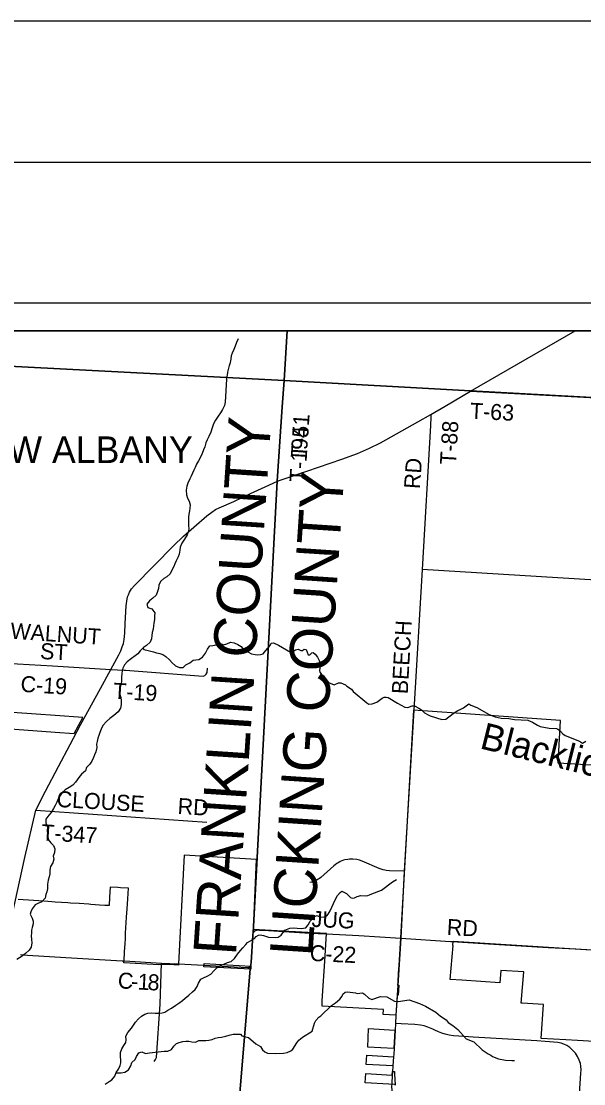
# Model space of a CAD drawing. Extents: x 0 to 91.3, y -0.7 to 22.
# Drawn here: x 4.012 to 6.008, y 18.226 to 22 of the extents above; entities that cross this region are included whole.
import ezdxf

# ---------------------------------------------------------------- set-up
doc = ezdxf.new("R2010")
doc.units = 0
for name, color, linetype in [('GM_X_City_Street', 7, 'Continuous'), ('GM_X_Corporation', 7, 'Continuous'), ('GM_X_Corporation_Text', 7, 'Continuous'), ('GM_X_County_Road', 7, 'Continuous'), ('GM_X_County_Road_Text', 7, 'Continuous'), ('GM_X_County_Text', 7, 'Continuous'), ('GM_X_Minor_River', 7, 'Continuous'), ('GM_X_Minor_River_Text', 7, 'Continuous'), ('GM_X_Township_Road', 7, 'Continuous'), ('GM_X_Township_Road_Text', 7, 'Continuous'), ('GM_X_US_Route', 7, 'Continuous'), ('SH_Border', 7, 'Continuous'), ('SH_Cut_Line', 7, 'Continuous'), ('SH_Data', 7, 'Continuous')]:
    doc.layers.add(name, color=color, linetype=linetype)

msp = doc.modelspace()

# ---------------------------------------------------------------- linework, layer by layer
at = {"layer": 'GM_X_City_Street'}
for points in [[(4.4838, 18.305), (4.4887, 18.3117), (4.492, 18.3195), (4.5045, 18.5078), (4.5099, 18.6546)], [(5.992, 18.1725), (5.9979, 18.2633), (5.9982, 18.2753), (5.9973, 18.2876), (5.9959, 18.2976), (5.992, 18.3093), (5.9862, 18.3221), (5.9787, 18.3341), (5.9686, 18.3455), (5.958, 18.3545), (5.9477, 18.3612), (5.9374, 18.3667), (5.9274, 18.3695), (5.9157, 18.372), (5.8708, 18.3756), (5.8418, 18.3776), (5.6158, 18.3912), (5.5645, 18.3943), (5.5453, 18.3957), (5.5303, 18.3985), (5.5161, 18.4021), (5.5038, 18.4052), (5.4921, 18.4102), (5.4798, 18.4163), (5.4723, 18.42), (5.4548, 18.4269), (5.4417, 18.4311), (5.4283, 18.4339), (5.4082, 18.4361), (5.3603, 18.4389), (5.3397, 18.44)]]:
    msp.add_lwpolyline(points, dxfattribs=at)
at = {"layer": 'GM_X_Corporation'}
for points in [[(4.9555, 20.9), (2.1, 20.9), (2.1, 20.8844), (2.3878, 20.8673), (3.0994, 20.8263), (3.2209, 20.8181), (3.3908, 20.8093), (3.4006, 20.8086), (3.9216, 20.777), (4.9448, 20.7239)], [(4.9555, 20.9), (2.1, 20.9), (2.1, 20.8844), (2.3878, 20.8673), (3.0994, 20.8263), (3.2209, 20.8181), (3.3908, 20.8093), (3.4006, 20.8086), (3.9216, 20.777), (4.9448, 20.7239)], [(8.9, 20.4953), (8.9, 20.9), (4.9555, 20.9), (4.9448, 20.7239), (5.6061, 20.6867), (6.253, 20.6521), (6.6637, 20.6293), (7.0477, 20.6033), (7.5521, 20.5793), (8.3956, 20.5276), (8.8785, 20.4965)], [(4.6607, 18.6526), (4.8269, 18.6431), (4.8262, 18.6322), (4.6603, 18.6415), (4.6603, 18.6415)], [(5.2447, 18.4218), (5.338, 18.4165), (5.334, 18.3504), (5.2412, 18.3558)], [(5.2384, 18.3274), (5.3323, 18.3216), (5.3303, 18.289), (5.2363, 18.2945)], [(5.3367, 18.261), (5.3388, 18.2209), (5.3387, 18.2227), (5.316, 18.2244), (5.2323, 18.2289), (5.2343, 18.2618), (5.3284, 18.2562), (5.3292, 18.2694), (5.3367, 18.2689)]]:
    msp.add_lwpolyline(points, close=True, dxfattribs=at)
for points in [[(4.7833, 18.1361), (4.8242, 18.6326), (4.8251, 18.6439), (4.8263, 18.646), (4.8271, 18.6491), (4.8277, 18.656), (4.8336, 18.7529), (4.834, 18.7568), (4.8352, 18.7619), (4.9205, 20.3667), (4.9376, 20.6305), (4.9448, 20.7239), (3.9216, 20.777), (3.4006, 20.8086), (3.3908, 20.8093), (3.2209, 20.8181), (3.0994, 20.8263), (2.3878, 20.8673), (2.1, 20.8844), (2.1, 14.1)], [(4.7833, 18.1361), (4.8242, 18.6326), (4.8251, 18.6439), (4.8263, 18.646), (4.8271, 18.6491), (4.8277, 18.656), (4.8336, 18.7529), (4.834, 18.7568), (4.8352, 18.7619), (4.9205, 20.3667), (4.9376, 20.6305), (4.9448, 20.7239), (3.9216, 20.777), (3.4006, 20.8086), (3.3908, 20.8093), (3.2209, 20.8181), (3.0994, 20.8263), (2.3878, 20.8673), (2.1, 20.8844), (2.1, 15.7138)], [(8.9, 14.1), (8.9, 20.9), (4.9555, 20.9), (4.9448, 20.7239), (4.9376, 20.6305), (4.9205, 20.3667), (4.8352, 18.7619), (4.834, 18.7568), (4.8336, 18.7529), (4.8277, 18.656), (4.8271, 18.6491), (4.8263, 18.646), (4.8251, 18.6439), (4.8242, 18.6326), (4.7833, 18.1361)], [(8.9, 15.2596), (8.9, 20.4953), (8.8785, 20.4965), (8.3956, 20.5276), (7.5521, 20.5793), (7.0477, 20.6033), (6.6637, 20.6293), (6.253, 20.6521), (5.6061, 20.6867), (4.9448, 20.7239), (4.9376, 20.6305), (4.9205, 20.3667), (4.8352, 18.7619), (4.834, 18.7568), (4.8336, 18.7529), (4.8277, 18.656), (4.8271, 18.6491), (4.8263, 18.646), (4.8251, 18.6439), (4.8242, 18.6326), (4.7833, 18.1361)], [(6.4311, 19.3332), (5.9167, 19.3643), (5.9255, 19.5165), (5.4044, 19.5531), (5.3577, 18.744), (5.353, 18.6658), (5.3518, 18.6467), (5.35, 18.6169), (5.3483, 18.5875), (5.3469, 18.5764), (5.352, 18.5761), (5.3498, 18.5405), (5.3457, 18.5407), (5.3444, 18.5224), (5.3433, 18.5047), (5.3422, 18.4869), (5.3412, 18.4694), (5.2963, 18.4714), (5.2971, 18.4894), (5.0792, 18.5014), (5.0803, 18.5206), (5.0814, 18.5382), (5.0893, 18.6616), (5.0956, 18.7589), (5.0723, 18.7602), (4.9856, 18.765), (4.9761, 18.7655), (4.9479, 18.7671), (4.9196, 18.7687), (4.8772, 18.7711), (4.8358, 18.7734), (4.8359, 18.7742), (4.8465, 19.0226), (4.5906, 19.0377), (4.5703, 18.6519), (4.5699, 18.6465), (4.5532, 18.6475), (4.5203, 18.6493), (4.5004, 18.6481), (4.376, 18.6553), (4.3768, 18.6665), (4.377, 18.6705), (4.3779, 18.6856), (4.3785, 18.695), (4.3802, 18.7228), (4.3813, 18.7417), (4.3824, 18.7606), (4.3836, 18.7795), (4.3847, 18.7984), (4.3858, 18.8174), (4.3876, 18.8465), (4.3897, 18.8824), (4.3908, 18.9013), (4.392, 18.9204), (4.3636, 18.9219), (4.3541, 18.9224), (4.3275, 18.9238), (4.3264, 18.906), (4.3253, 18.8881), (4.3236, 18.8584), (4.3086, 18.8593), (4.2897, 18.8606), (4.2589, 18.8627), (4.2519, 18.8631), (4.2174, 18.8654), (4.1862, 18.8675), (4.1767, 18.8681), (4.1325, 18.8711), (4.121, 18.8718), (4.0917, 18.8738), (4.0013, 18.8798)], [(3.8922, 19.4929), (4.1325, 19.475), (4.1996, 19.4699), (4.215, 19.4983), (4.2305, 19.5269), (4.1325, 19.5337), (4.0647, 19.5386), (3.9805, 19.5443)], [(6.045, 18.3762), (5.986, 18.3796), (5.9443, 18.382), (5.8573, 18.3869), (5.8648, 18.5077), (5.7899, 18.5122), (5.7859, 18.5125), (5.7955, 18.6235), (5.7138, 18.6282), (5.7104, 18.5841), (5.5748, 18.5934), (5.5342, 18.5965), (5.5448, 18.7169), (5.5439, 18.7169), (5.5451, 18.7322), (6.3918, 18.6787)]]:
    msp.add_lwpolyline(points, dxfattribs=at)
at = {"layer": 'GM_X_County_Road'}
for p, q in [((4.945, 20.7234), (4.9557, 20.9)), ((5.3586, 18.7432), (5.5353, 18.731)), ((4.5698, 18.6514), (4.6596, 18.6465))]:
    msp.add_line(p, q, dxfattribs=at)
for points in [[(3.8207, 19.7276), (3.8606, 19.7255), (3.9577, 19.7193), (4.1234, 19.7106), (4.3298, 19.697)], [(4.8253, 18.6433), (4.8265, 18.6455), (4.8273, 18.6485), (4.828, 18.6555), (4.8338, 18.7524), (4.8342, 18.7562), (4.8354, 18.7613)], [(4.8354, 18.7613), (4.8382, 18.7657), (4.8413, 18.7685), (4.8445, 18.7703), (4.8475, 18.7714), (4.851, 18.7719), (4.8569, 18.7718), (4.8896, 18.7699), (5.0362, 18.761), (5.0949, 18.758)], [(5.0949, 18.758), (5.2094, 18.7522), (5.3586, 18.7432)], [(5.5353, 18.731), (5.5363, 18.731), (5.5413, 18.7306), (5.6887, 18.7219), (5.882, 18.71), (5.98, 18.7044), (6.1355, 18.6949), (6.3006, 18.6844), (6.3651, 18.68), (6.3921, 18.6782)], [(4.0096, 18.6845), (4.0345, 18.6828), (4.1701, 18.6744), (4.3697, 18.6624)], [(4.3697, 18.6624), (4.3787, 18.6619), (4.5099, 18.6546), (4.5698, 18.6514)], [(4.6596, 18.6465), (4.7674, 18.6407), (4.8159, 18.6386), (4.8192, 18.6389), (4.8222, 18.6406), (4.8241, 18.6422), (4.8253, 18.6433)]]:
    msp.add_lwpolyline(points, dxfattribs=at)
at = {"layer": 'GM_X_Minor_River'}
for points in [[(4.7407, 20.7285), (4.744, 20.7428), (4.7455, 20.7535), (4.7488, 20.7675), (4.7514, 20.777), (4.754, 20.7873), (4.7566, 20.7998), (4.7585, 20.8124), (4.7611, 20.8223), (4.7678, 20.8356), (4.7727, 20.847), (4.7768, 20.8603), (4.7828, 20.8732)], [(4.7407, 20.7285), (4.736, 20.6464), (4.7336, 20.6351), (4.726, 20.6211), (4.7194, 20.6093), (4.7103, 20.5973), (4.7011, 20.5829), (4.6945, 20.5696), (4.6895, 20.5552), (4.6841, 20.5401), (4.6779, 20.5253), (4.6722, 20.5125), (4.6675, 20.5019), (4.6629, 20.4882), (4.6583, 20.4776), (4.654, 20.4648), (4.6471, 20.4496), (4.641, 20.439), (4.634, 20.4262), (4.629, 20.4152), (4.6248, 20.4054), (4.6198, 20.3948), (4.6148, 20.3845), (4.6098, 20.3747), (4.6036, 20.3596), (4.5998, 20.3486), (4.5974, 20.3338), (4.5981, 20.3182), (4.6018, 20.3061), (4.6074, 20.2954), (4.6108, 20.2817), (4.6107, 20.2707), (4.6091, 20.2609), (4.6068, 20.2495), (4.6059, 20.2381), (4.6051, 20.2226), (4.6054, 20.2074), (4.6061, 20.1979), (4.6052, 20.1884), (4.6006, 20.1755), (4.591, 20.16), (4.5814, 20.1464), (4.576, 20.1317), (4.5752, 20.121), (4.5728, 20.1074), (4.5686, 20.0972), (4.5621, 20.0832), (4.5571, 20.0726), (4.5532, 20.0627), (4.5467, 20.0506), (4.5398, 20.0374), (4.5283, 20.0261), (4.5184, 20.0208), (4.5062, 20.0103), (4.5004, 19.9966), (4.4988, 19.9845), (4.4957, 19.9746), (4.4907, 19.9614), (4.4789, 19.9501), (4.4671, 19.9407), (4.4575, 19.9297), (4.4608, 19.9179), (4.4749, 19.9133), (4.4854, 19.8988), (4.4849, 19.8882), (4.4845, 19.8753), (4.4829, 19.8616), (4.4817, 19.8518), (4.4797, 19.8408), (4.4766, 19.8283), (4.4758, 19.818), (4.4738, 19.8067), (4.4699, 19.7938), (4.4566, 19.7825), (4.4455, 19.7749), (4.4341, 19.7633), (4.426, 19.7534), (4.4161, 19.7455), (4.4035, 19.7357), (4.3879, 19.7244), (4.378, 19.7139), (4.3726, 19.7025), (4.3706, 19.6923), (4.3687, 19.6828), (4.3678, 19.6699), (4.3677, 19.6559), (4.3669, 19.6464), (4.3615, 19.6312), (4.3592, 19.6184), (4.3614, 19.6089), (4.3651, 19.5978), (4.3666, 19.5868), (4.3668, 19.5728), (4.3645, 19.5603), (4.3564, 19.547), (4.3404, 19.5335), (4.3263, 19.5233), (4.3145, 19.5127), (4.3019, 19.4988), (4.2953, 19.4852), (4.2903, 19.473)], [(4.4433, 19.7726), (4.4474, 19.7681), (4.4618, 19.765), (4.4716, 19.7619), (4.4815, 19.7599), (4.4917, 19.7565), (4.5035, 19.7541), (4.5148, 19.7503), (4.525, 19.7437), (4.5382, 19.7315), (4.5477, 19.7208), (4.5597, 19.7098), (4.573, 19.7044), (4.5859, 19.7039), (4.5962, 19.7133), (4.6099, 19.7209), (4.6225, 19.7303), (4.632, 19.7317), (4.6415, 19.7328), (4.6548, 19.7415), (4.6659, 19.7551), (4.6728, 19.7694), (4.6809, 19.7815), (4.6915, 19.7826), (4.7037, 19.7848), (4.7147, 19.7923), (4.7295, 19.7854), (4.7413, 19.788), (4.7542, 19.794), (4.7671, 19.792), (4.78, 19.7866), (4.7921, 19.7794), (4.8019, 19.7672), (4.8162, 19.7602), (4.8291, 19.7533), (4.8416, 19.7506), (4.8511, 19.7494), (4.861, 19.7505), (4.8705, 19.7531), (4.8793, 19.7648)], [(4.8793, 19.7648), (4.8953, 19.7821), (4.8983, 19.7904), (4.9067, 19.7919), (4.9245, 19.7838), (4.9676, 19.7593), (4.9741, 19.7597), (4.9794, 19.7631), (4.9847, 19.7668), (4.9942, 19.7694), (5.0041, 19.7645), (5.0098, 19.7644), (5.0155, 19.7693), (5.0231, 19.7682), (5.0298, 19.7488), (5.0359, 19.7491), (5.0427, 19.7559), (5.048, 19.7574), (5.0548, 19.7521), (5.0631, 19.741), (5.0691, 19.7288), (5.0729, 19.7167), (5.0732, 19.7095), (5.0697, 19.6931), (5.0716, 19.6874), (5.0757, 19.6817), (5.0848, 19.6752), (5.1025, 19.6512), (5.1226, 19.6428), (5.1382, 19.6495), (5.1465, 19.6495), (5.1624, 19.6433), (5.1677, 19.638), (5.1836, 19.6269), (5.1896, 19.6185), (5.2383, 19.5784), (5.2459, 19.5739), (5.2577, 19.5749), (5.2736, 19.5809), (5.2931, 19.5953), (5.2995, 19.5986), (5.3071, 19.5994), (5.3143, 19.5982), (5.3476, 19.5779), (5.3726, 19.5634), (5.3836, 19.5622), (5.3992, 19.5682), (5.4075, 19.5677), (5.4226, 19.5601), (5.4317, 19.5536), (5.4427, 19.5429), (5.4555, 19.536), (5.4631, 19.5322), (5.504, 19.5198), (5.5181, 19.5209), (5.5447, 19.5413), (5.5607, 19.5514), (5.5691, 19.5552)], [(5.5691, 19.5552), (5.5811, 19.5609), (5.5998, 19.5756), (5.6073, 19.5702), (5.6281, 19.5618), (5.6727, 19.5369), (5.6935, 19.5288), (5.7144, 19.5245), (5.7424, 19.5232), (5.7625, 19.5193), (5.8098, 19.5171), (5.8257, 19.5105), (5.8439, 19.4994), (5.8537, 19.4952), (5.8851, 19.4893), (5.9109, 19.4877), (5.9158, 19.4857), (5.9219, 19.4819), (5.9343, 19.4686), (5.9426, 19.4632), (5.9929, 19.4421), (6.0031, 19.4356), (6.0153, 19.4431)], [(4.2903, 19.473), (4.2868, 19.4628), (4.2841, 19.4533), (4.281, 19.4416), (4.2791, 19.4317), (4.2801, 19.42), (4.277, 19.4052), (4.272, 19.3942), (4.2681, 19.3844), (4.2624, 19.3715), (4.2555, 19.3605), (4.2436, 19.3492), (4.2394, 19.3371), (4.2253, 19.3258), (4.2161, 19.313), (4.205, 19.2975), (4.195, 19.2858), (4.1817, 19.2779), (4.1672, 19.2692), (4.1577, 19.2605), (4.1481, 19.2462), (4.1416, 19.2356), (4.1377, 19.2254), (4.1323, 19.214), (4.1258, 19.2038), (4.1181, 19.1898), (4.1101, 19.18), (4.099, 19.166), (4.0986, 19.1531), (4.1045, 19.1379), (4.1041, 19.1235), (4.1062, 19.1064), (4.1077, 19.0939), (4.1167, 19.0817), (4.1269, 19.0725), (4.1314, 19.0596), (4.1294, 19.0471), (4.1255, 19.0346), (4.1281, 19.0239), (4.1242, 19.0103), (4.1154, 18.9974), (4.1138, 18.9842), (4.1134, 18.9716), (4.1114, 18.9606), (4.1079, 18.9493), (4.1048, 18.9341), (4.1047, 18.9182), (4.1023, 18.908), (4.0989, 18.8981), (4.0973, 18.8852), (4.0847, 18.8716), (4.0713, 18.8664), (4.0614, 18.8608), (4.0507, 18.8475), (4.0457, 18.8369), (4.0434, 18.8275), (4.0505, 18.8134), (4.0539, 18.8027), (4.0542, 18.7933), (4.0507, 18.7808), (4.0487, 18.7709), (4.0479, 18.761), (4.0475, 18.7516), (4.0485, 18.7383), (4.05, 18.7257), (4.0468, 18.7113), (4.0399, 18.6996), (4.0273, 18.6879), (4.0148, 18.6793), (3.9968, 18.6668)], [(4.8148, 18.727), (4.84, 18.7416), (4.8461, 18.7484), (4.8541, 18.754), (4.8594, 18.7551), (4.8719, 18.7528), (4.8897, 18.7463), (4.9124, 18.7446), (4.9231, 18.7465), (4.9341, 18.754), (4.9471, 18.771), (4.965, 18.7778), (4.9764, 18.7796), (5.0052, 18.7776), (5.0212, 18.7794), (5.0299, 18.7907), (5.0372, 18.8028), (5.0525, 18.8195), (5.0616, 18.8228), (5.0752, 18.8178), (5.0874, 18.8185), (5.0961, 18.8227), (5.1007, 18.8276), (5.108, 18.8401), (5.126, 18.8791), (5.1345, 18.8938), (5.1436, 18.9052), (5.1497, 18.9097), (5.166, 18.902), (5.18, 18.8875), (5.1856, 18.8849), (5.1944, 18.8856), (5.2039, 18.8912), (5.2168, 18.8942), (5.2324, 18.8934), (5.2419, 18.8944), (5.2479, 18.8971), (5.2555, 18.9001), (5.2901, 18.9128), (5.3298, 18.9434), (5.3435, 18.9509)], [(4.3099, 18.2244), (4.3236, 18.2342), (4.3331, 18.2391), (4.3438, 18.2523), (4.3492, 18.2652), (4.3569, 18.2773), (4.3626, 18.2901), (4.3654, 18.3004), (4.365, 18.3106), (4.3647, 18.3212), (4.3641, 18.3368), (4.3687, 18.35), (4.3764, 18.3614), (4.3825, 18.372), (4.3845, 18.3818), (4.3827, 18.3951), (4.3896, 18.408), (4.4033, 18.4235), (4.4106, 18.434), (4.4179, 18.4443), (4.4278, 18.4567), (4.4381, 18.4654), (4.4507, 18.4729), (4.4606, 18.4763), (4.4727, 18.4773), (4.4872, 18.4765), (4.5001, 18.4764), (4.5122, 18.4775), (4.5217, 18.4805), (4.5324, 18.4868), (4.5453, 18.4947), (4.5602, 18.5049), (4.5712, 18.512), (4.5838, 18.5214), (4.5938, 18.5294), (4.6071, 18.5407), (4.6201, 18.5516), (4.6296, 18.5599), (4.6358, 18.5709), (4.6408, 18.583), (4.6496, 18.5966), (4.6591, 18.6022), (4.672, 18.6074), (4.6842, 18.6146), (4.6957, 18.6267), (4.7075, 18.6387), (4.7205, 18.6466), (4.7311, 18.6507), (4.7441, 18.6564), (4.7574, 18.6605), (4.7688, 18.6706), (4.7788, 18.6857), (4.7895, 18.699), (4.7987, 18.7088), (4.8094, 18.7209), (4.8148, 18.727)], [(4.7942, 18.3963), (4.8179, 18.3894), (4.844, 18.3673), (4.8607, 18.3585), (4.8682, 18.3467), (4.8761, 18.339), (4.8863, 18.3341), (4.9144, 18.3332), (4.9429, 18.3338), (4.9558, 18.3367), (4.9683, 18.342), (4.976, 18.3488), (4.9901, 18.3715), (4.9974, 18.3806), (5.0027, 18.3847), (5.0103, 18.3908), (5.0438, 18.4122), (5.0523, 18.4414), (5.0569, 18.4501), (5.068, 18.4626), (5.0753, 18.4664), (5.1123, 18.5041), (5.1271, 18.5135), (5.142, 18.5264), (5.1504, 18.5373), (5.1535, 18.5442), (5.1615, 18.5509), (5.1691, 18.5524), (5.1979, 18.5485), (5.2039, 18.5462), (5.2229, 18.5484), (5.2305, 18.5434), (5.2448, 18.53), (5.2562, 18.5247), (5.2866, 18.5355), (5.3097, 18.5339), (5.3362, 18.5193), (5.3495, 18.5178), (5.3886, 18.5236), (5.4254, 18.5113), (5.4465, 18.5017), (5.4836, 18.4795), (5.4995, 18.4658), (5.5199, 18.4524), (5.5274, 18.4432), (5.5437, 18.4329), (5.5611, 18.418)], [(4.3489, 18.2644), (4.3667, 18.2639), (4.38, 18.2673), (4.3929, 18.2751), (4.4013, 18.2888), (4.4048, 18.3013), (4.4163, 18.3122), (4.4213, 18.3224), (4.429, 18.3357), (4.4404, 18.339), (4.4532, 18.3329), (4.4665, 18.3351), (4.4772, 18.3365), (4.4874, 18.3376), (4.4981, 18.339), (4.5079, 18.3401), (4.5189, 18.3416), (4.5319, 18.3419), (4.5452, 18.3475), (4.5528, 18.3588), (4.5624, 18.369), (4.5723, 18.372), (4.5856, 18.3753), (4.5962, 18.3772), (4.6068, 18.3771), (4.6171, 18.3751), (4.63, 18.3736), (4.6425, 18.3788), (4.657, 18.3795), (4.6668, 18.3798), (4.6775, 18.3809), (4.6889, 18.3831), (4.6999, 18.3872), (4.7102, 18.3898), (4.7227, 18.3908), (4.7375, 18.3942), (4.7497, 18.3986), (4.7637, 18.4016), (4.7766, 18.4023), (4.7899, 18.4022), (4.7942, 18.3963)], [(5.5611, 18.418), (5.5904, 18.3856), (5.6177, 18.374), (5.6471, 18.3466), (5.669, 18.3324), (5.6788, 18.327), (5.6837, 18.3225), (5.7057, 18.3147), (5.7307, 18.3097), (5.753, 18.308), (5.7625, 18.3087)]]:
    msp.add_lwpolyline(points, dxfattribs=at)
at = {"layer": 'GM_X_Township_Road'}
for p, q in [((4.0635, 19.1971), (4.671, 19.1554)), ((5.3586, 18.7432), (5.3481, 18.5748)), ((5.3456, 18.5352), (5.3415, 18.4698)), ((5.3384, 18.4162), (5.3349, 18.3505)), ((5.3333, 18.3227), (5.3309, 18.2887)), ((5.3287, 18.2567), (5.3266, 18.2269)), ((5.3294, 18.2667), (5.3287, 18.2567))]:
    msp.add_line(p, q, dxfattribs=at)
for points in [[(4.9208, 20.3662), (4.9378, 20.63), (4.945, 20.7234)], [(5.6063, 20.6862), (6.2532, 20.6515), (6.6639, 20.6288), (7.0479, 20.6028), (7.5524, 20.5788), (8.3958, 20.527), (8.8787, 20.4959), (8.9, 20.4948)], [(5.4652, 20.6032), (5.4659, 20.594), (5.4641, 20.5635), (5.4342, 20.0523), (5.4046, 19.5524)], [(8.9, 19.6421), (8.0368, 19.6987), (7.548, 19.73), (7.5299, 19.732), (7.5234, 19.7353), (7.5204, 19.743), (7.5209, 19.758), (7.5287, 19.9131), (7.5284, 19.9207), (7.5264, 19.9252), (7.5209, 19.9272), (7.5111, 19.9282), (7.2951, 19.9402), (7.0134, 19.9559), (5.4342, 20.0523)], [(4.3298, 19.697), (4.3775, 19.6949), (4.3817, 19.6946)], [(4.3817, 19.6946), (4.6572, 19.6735), (4.6636, 19.6754), (4.6686, 19.6812), (4.6712, 19.6861), (4.6723, 19.7017)], [(5.4046, 19.5524), (5.3708, 18.9806), (5.3586, 18.7432)], [(5.3708, 18.9806), (5.3184, 18.9825), (5.307, 18.9833), (5.3017, 18.9842), (5.2962, 18.9854), (5.2861, 18.9887), (5.2823, 18.9901), (5.2211, 19.0161), (5.2123, 19.0194), (5.2023, 19.0219), (5.1891, 19.0236), (5.1766, 19.0235), (5.1708, 19.0228), (5.1604, 19.0208), (5.1556, 19.0194), (5.1497, 19.0174), (5.1436, 19.0148), (5.1385, 19.0122), (5.1337, 19.0095), (5.1286, 19.0061), (5.1255, 19.0039), (5.1208, 19), (5.0751, 18.9588), (5.0699, 18.9547), (5.0659, 18.9519), (5.0604, 18.9487), (5.054, 18.9457), (5.0484, 18.9436), (5.0429, 18.9421), (5.0365, 18.9408)], [(5.3481, 18.5748), (5.3459, 18.5401), (5.3456, 18.5352)], [(5.3415, 18.4698), (5.3397, 18.44), (5.3384, 18.4162)], [(5.3349, 18.3505), (5.3338, 18.3297), (5.3333, 18.3227)], [(5.3309, 18.2887), (5.3295, 18.2687), (5.3294, 18.2667)], [(5.3266, 18.2269), (5.3257, 18.2149), (5.3287, 18.1931), (5.3299, 18.1879)]]:
    msp.add_lwpolyline(points, dxfattribs=at)
at = {"layer": 'GM_X_US_Route'}
msp.add_line((5.6063, 20.6862), (5.9773, 20.9), dxfattribs=at)
for points in [[(4.9208, 20.3662), (4.931, 20.3698), (4.9412, 20.3733), (5.0259, 20.4021), (5.1498, 20.4449), (5.2056, 20.4643), (5.248, 20.4832), (5.2865, 20.5027), (5.4189, 20.577), (5.4652, 20.6032), (5.5167, 20.6332), (5.6063, 20.6862)], [(4.0985, 19.2652), (4.1436, 19.353), (4.1856, 19.4313), (4.2223, 19.5003), (4.2936, 19.6299), (4.3298, 19.697), (4.3577, 19.7495), (4.3648, 19.7633), (4.3706, 19.7774), (4.3744, 19.7891), (4.3774, 19.8035), (4.3793, 19.826), (4.3812, 19.8605), (4.3844, 19.9238), (4.3864, 19.9401), (4.3894, 19.9548), (4.392, 19.9628), (4.3957, 19.9715), (4.4035, 19.984), (4.4133, 19.9953), (4.552, 20.1369), (4.5882, 20.1712), (4.6244, 20.2033), (4.671, 20.2434), (4.6877, 20.2559), (4.7012, 20.2653), (4.7146, 20.272), (4.7658, 20.2945), (4.8256, 20.3223), (4.8776, 20.3463), (4.9208, 20.3662)], [(3.9807, 18.8292), (4.0247, 19.0288), (4.0635, 19.1971), (4.0985, 19.2652)]]:
    msp.add_lwpolyline(points, dxfattribs=at)
at = {"layer": 'SH_Border'}
msp.add_lwpolyline([(1.5, 21.5), (33.5, 21.5), (33.5, 0.5), (1.5, 0.5)], close=True, dxfattribs=at)
at = {"layer": 'SH_Cut_Line'}
msp.add_lwpolyline([(0, 0), (34, 0), (34, 22), (0, 22)], close=True, dxfattribs=at)
at = {"layer": 'SH_Data'}
for p, q in [((2, 21), (9, 21)), ((2.1, 20.9), (8.9, 20.9))]:
    msp.add_line(p, q, dxfattribs=at)

# ---------------------------------------------------------------- texts
at = {"layer": 'GM_X_Corporation_Text'}
msp.add_text('NEW ALBANY', height=0.0947, rotation=0, dxfattribs=at).set_placement((3.7903, 20.4305))
at = {"layer": 'GM_X_County_Road_Text'}
for s, height, rotation, p in [('WALNUT', 0.05682, 356.0379, (3.9721, 19.8068)), ('ST', 0.05682, 356.5316, (4.0775, 19.735)), ('C-19', 0.05682, 356.3223, (4.0082, 19.6183)), ('JUG', 0.05682, 357.3805, (5.0416, 18.7832)), ('RD', 0.05682, 356.578, (5.5208, 18.7548)), ('C-22', 0.05682, 357.2576, (5.035, 18.6622)), ('C', 0.0568, 355.824, (4.3531, 18.5654)), ('1', 0.0568, 356.8812, (4.4241, 18.5606)), ('8', 0.0568, 356.926, (4.4591, 18.5587)), ('-', 0.0568, 356.7826, (4.4007, 18.5619))]:
    msp.add_text(s, height=height, rotation=rotation, dxfattribs=at).set_placement(p)
at = {"layer": 'GM_X_County_Text'}
for s, p in [('FRANKLIN COUNTY', (4.7735, 18.6791)), ('LICKING COUNTY', (5.045, 18.6754))]:
    msp.add_text(s, height=0.151515, rotation=86.2274, dxfattribs=at).set_placement(p)
at = {"layer": 'GM_X_Minor_River_Text'}
msp.add_text('Blacklick', height=0.0947, rotation=346.0026, dxfattribs=at).set_placement((5.6354, 19.418))
at = {"layer": 'GM_X_Township_Road_Text'}
for s, rotation, p in [('T-63', 357.1555, (5.6032, 20.5882)), ('T-51', 86.1149, (5.0248, 20.4475)), ('T-88', 86.4669, (5.554, 20.4231)), ('T-194', 86.6332, (5.0202, 20.3619)), ('RD', 86.0208, (5.4266, 20.3374)), ('BEECH', 86.8551, (5.3832, 19.6087)), ('T-19', 356.4582, (4.337, 19.5936)), ('CLOUSE', 356.6334, (4.1364, 19.2092)), ('RD', 356.5467, (4.5656, 19.1842)), ('T-347', 356.6167, (4.0818, 19.0909))]:
    msp.add_text(s, height=0.05682, rotation=rotation, dxfattribs=at).set_placement(p)

doc.saveas('drawing.dxf')
